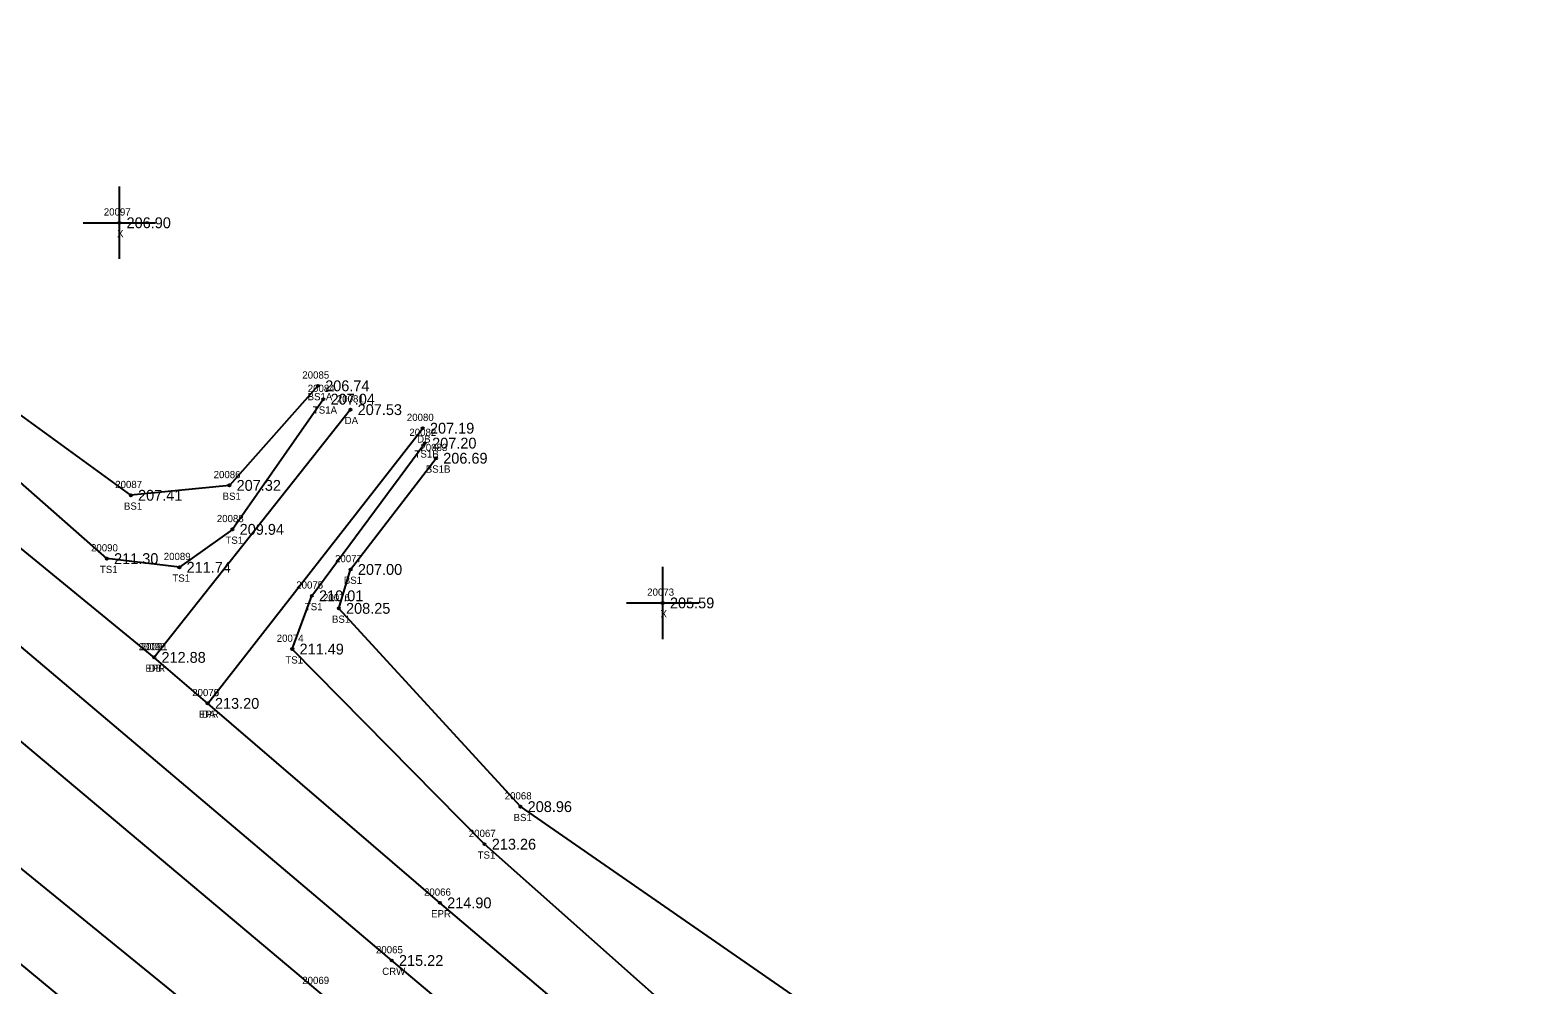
# Model space of a CAD drawing. Extents: x 2260230 to 2261304, y 1064626 to 1065587.
# Drawn here: x 2260916.2 to 2261124.9, y 1064943.4 to 1065075.6 of the extents above; entities that cross this region are included whole.
import ezdxf

# ---------------------------------------------------------------- set-up
doc = ezdxf.new("R2010")
doc.units = 0
for name, color, linetype in [('RD_DTM_BkLn1', 7, 'Continuous'), ('RD_DTM_BkLn2', 7, 'Continuous'), ('RD_DTM_BkLn_txCode', 7, 'Continuous'), ('RD_EX_Driveway', 7, 'Continuous'), ('RD_EX_Driveway_txCode', 7, 'Continuous'), ('RD_EX_Misc', 7, 'Continuous'), ('RD_EX_Misc_txCode', 7, 'Continuous'), ('RD_EX_Road', 7, 'Continuous'), ('RD_EX_Road_txCode', 7, 'Continuous'), ('RD_EX_TX_Driveway_ELEV', 7, 'Continuous'), ('RD_EX_TX_Misc_ELEV', 7, 'Continuous'), ('RD_EX_TX_Road_ELEV', 7, 'Continuous'), ('RD_HC_Survey_ELEV', 7, 'Continuous'), ('RD_HC_Survey_txCode', 7, 'Continuous'), ('RD_SMD_Locator', 7, 'Continuous')]:
    doc.layers.add(name, color=color, linetype=linetype)

msp = doc.modelspace()

# ---------------------------------------------------------------- linework, layer by layer
at = {"layer": 'RD_DTM_BkLn1'}
msp.add_lwpolyline([(2261119.39, 1064818.57), (2261039.33, 1064885.27), (2260966.22, 1064946.78), (2260891.14, 1065010.3), (2260825.73, 1065065.53)], dxfattribs=at)
at = {"layer": 'RD_DTM_BkLn2'}
for points in [[(2260956, 1065026.37), (2260943.74, 1065012.58), (2260930.09, 1065011.21), (2260907.19, 1065027.84), (2260853.85, 1065071.62), (2260836.25, 1065093.94)], [(2260956.75, 1065024.52), (2260944.16, 1065006.49), (2260936.81, 1065001.24), (2260926.77, 1065002.44), (2260902.81, 1065023.49), (2260850.27, 1065067.66), (2260843.76, 1065078.29), (2260839.71, 1065074.22), (2260834.92, 1065077.53)], [(2261107.5, 1064803.56), (2261026.54, 1064870.98), (2260948.4, 1064932.24), (2260874.38, 1064992.47), (2260842.04, 1065014.91), (2260817.83, 1065046.66), (2260820.04, 1065048.66), (2260815.22, 1065054.09)], [(2261101.75, 1064796.17), (2261015.65, 1064858.96), (2260944.13, 1064922.06), (2260868.1, 1064985.02), (2260817.12, 1065034.76), (2260812.18, 1065041.52), (2260806.25, 1065051.8)], [(2261085.26, 1064917.31), (2261064.5, 1064893.2), (2261059.96, 1064891.02), (2260979.07, 1064962.89), (2260952.45, 1064989.91), (2260955.15, 1064997.29), (2260970.81, 1065018.43)], [(2261033.32, 1064933.97), (2260984.04, 1064968.09), (2260958.89, 1064995.55), (2260960.53, 1065000.94), (2260972.35, 1065016.34)]]:
    msp.add_lwpolyline(points, dxfattribs=at)
at = {"layer": 'RD_EX_Driveway'}
for p, q in [((2260960.5, 1065023.07), (2260933.33, 1064988.76)), ((2260940.74, 1064982.39), (2260970.51, 1065020.5))]:
    msp.add_line(p, q, dxfattribs=at)
at = {"layer": 'RD_EX_Misc'}
for p, q in [((2260928.5, 1065043.95), (2260928.5, 1065053.95)), ((2260923.5, 1065048.95), (2260933.5, 1065048.95)), ((2261003.74, 1064991.3), (2261003.74, 1065001.3)), ((2260998.74, 1064996.3), (2261008.74, 1064996.3))]:
    msp.add_line(p, q, dxfattribs=at)
at = {"layer": 'RD_EX_Road'}
for points in [[(2261124.91, 1064827.37), (2261072.16, 1064871.6), (2261053.72, 1064886.47), (2261045.58, 1064893.1), (2260972.89, 1064954.76), (2260940.74, 1064982.39), (2260933.33, 1064988.76), (2260898.06, 1065017.6), (2260832.89, 1065075.07)], [(2261112.68, 1064810.86), (2261032.95, 1064877.72), (2260956.01, 1064942.53), (2260884.53, 1065002.6), (2260818.6, 1065058.26)]]:
    msp.add_lwpolyline(points, dxfattribs=at)
at = {"layer": 'RD_SMD_Locator'}
for centre in [(2260928.5, 1065048.95), (2260956, 1065026.37), (2260956.75, 1065024.52), (2260960.5, 1065023.07), (2260970.51, 1065020.5), (2260970.81, 1065018.43), (2260972.35, 1065016.34), (2260943.74, 1065012.58), (2260930.09, 1065011.21), (2260944.16, 1065006.49), (2260926.77, 1065002.44), (2260936.81, 1065001.24), (2260960.53, 1065000.94), (2260955.15, 1064997.29), (2260958.89, 1064995.55), (2261003.74, 1064996.3), (2260952.45, 1064989.91), (2260933.33, 1064988.76), (2260933.33, 1064988.76), (2260940.74, 1064982.39), (2260940.74, 1064982.39), (2260984.04, 1064968.09), (2260979.07, 1064962.89), (2260972.89, 1064954.76), (2260966.22, 1064946.78)]:
    msp.add_circle(centre, 0.15, dxfattribs=at)

# ---------------------------------------------------------------- texts
at = {"layer": 'RD_DTM_BkLn_txCode'}
for s, p in [('20085', (2260953.84, 1065027.37)), ('20084', (2260954.59, 1065025.52)), ('BS1A', (2260954.57, 1065024.37)), ('TS1A', (2260955.3, 1065022.52)), ('20082', (2260968.66, 1065019.43)), ('20083', (2260970.19, 1065017.34)), ('TS1B', (2260969.38, 1065016.43)), ('20086', (2260941.56, 1065013.58)), ('BS1B', (2260970.93, 1065014.34)), ('20087', (2260927.93, 1065012.21)), ('BS1', (2260929.14, 1065009.21)), ('BS1', (2260942.8, 1065010.58)), ('20088', (2260942, 1065007.49)), ('20090', (2260924.58, 1065003.44)), ('TS1', (2260943.19, 1065004.49)), ('20089', (2260934.65, 1065002.24)), ('20077', (2260958.37, 1065001.94)), ('TS1', (2260925.81, 1065000.44)), ('TS1', (2260935.85, 1064999.24)), ('BS1', (2260959.58, 1064998.94)), ('20075', (2260953, 1064998.29)), ('20076', (2260956.7, 1064996.55)), ('TS1', (2260954.19, 1064995.29)), ('BS1', (2260957.94, 1064993.55)), ('20074', (2260950.29, 1064990.91)), ('TS1', (2260951.49, 1064987.91)), ('20068', (2260981.86, 1064969.09)), ('BS1', (2260983.09, 1064966.09)), ('20067', (2260976.89, 1064963.89)), ('TS1', (2260978.11, 1064960.89))]:
    msp.add_text(s, height=1, dxfattribs=at).set_placement(p)
at = {"layer": 'RD_EX_Driveway_txCode'}
for s, p in [('20081', (2260958.62, 1065024.07)), ('20080', (2260968.31, 1065021.5)), ('DA', (2260959.7, 1065021.07)), ('DB', (2260969.73, 1065018.5)), ('20091', (2260931.46, 1064989.76)), ('DB', (2260932.55, 1064986.76)), ('20079', (2260938.59, 1064983.39)), ('DA', (2260939.95, 1064980.39))]:
    msp.add_text(s, height=1, dxfattribs=at).set_placement(p)
at = {"layer": 'RD_EX_Misc_txCode'}
for s, p in [('20097', (2260926.35, 1065049.95)), ('X', (2260928.19, 1065046.95)), ('20073', (2261001.59, 1064997.3)), ('X', (2261003.43, 1064994.3))]:
    msp.add_text(s, height=1, dxfattribs=at).set_placement(p)
at = {"layer": 'RD_EX_Road_txCode'}
for s, p in [('20092', (2260931.18, 1064989.76)), ('EPR', (2260932.11, 1064986.76)), ('20078', (2260938.59, 1064983.39)), ('EPR', (2260939.52, 1064980.39)), ('20066', (2260970.69, 1064955.76)), ('EPR', (2260971.67, 1064952.76)), ('20069', (2260953.83, 1064943.53))]:
    msp.add_text(s, height=1, dxfattribs=at).set_placement(p)
at = {"layer": 'RD_EX_TX_Driveway_ELEV'}
for s, p in [('207.53', (2260961.5, 1065022.32)), ('207.19', (2260971.51, 1065019.75)), ('212.88', (2260934.33, 1064988.01)), ('213.20', (2260941.74, 1064981.64))]:
    msp.add_text(s, height=1.5, dxfattribs=at).set_placement(p)
at = {"layer": 'RD_EX_TX_Misc_ELEV'}
for s, p in [('206.90', (2260929.5, 1065048.2)), ('206.74', (2260957, 1065025.62)), ('207.04', (2260957.75, 1065023.77)), ('207.20', (2260971.81, 1065017.68)), ('206.69', (2260973.35, 1065015.59)), ('207.41', (2260931.09, 1065010.46)), ('207.32', (2260944.74, 1065011.83)), ('209.94', (2260945.16, 1065005.74)), ('211.30', (2260927.77, 1065001.69)), ('211.74', (2260937.81, 1065000.49)), ('207.00', (2260961.53, 1065000.19)), ('210.01', (2260956.15, 1064996.54)), ('208.25', (2260959.89, 1064994.8)), ('205.59', (2261004.74, 1064995.55)), ('211.49', (2260953.45, 1064989.16)), ('208.96', (2260985.04, 1064967.34)), ('213.26', (2260980.07, 1064962.14))]:
    msp.add_text(s, height=1.5, dxfattribs=at).set_placement(p)
at = {"layer": 'RD_EX_TX_Road_ELEV'}
for s, p in [('212.88', (2260934.33, 1064988.01)), ('213.20', (2260941.74, 1064981.64)), ('214.90', (2260973.89, 1064954.01))]:
    msp.add_text(s, height=1.5, dxfattribs=at).set_placement(p)
at = {"layer": 'RD_HC_Survey_ELEV'}
msp.add_text('215.22', height=1.5, dxfattribs=at).set_placement((2260967.22, 1064946.03))
at = {"layer": 'RD_HC_Survey_txCode'}
for s, p in [('20065', (2260964.04, 1064947.78)), ('CRW', (2260964.9, 1064944.78))]:
    msp.add_text(s, height=1, dxfattribs=at).set_placement(p)

doc.saveas('drawing.dxf')
